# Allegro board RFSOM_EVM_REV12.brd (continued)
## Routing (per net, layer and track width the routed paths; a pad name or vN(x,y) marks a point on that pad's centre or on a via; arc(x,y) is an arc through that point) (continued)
TX_03_N: length 58.2
  TOP w0.114: J1.G26 223.02,60.02 ; 187.76,91.38 187.54,91.15 arc(187.42,91.08) 187.29,91.05 186.86,91.05 arc(186.73,91.08) 186.62,91.15 LAB18.2 186.07,91.15 arc(185.96,91.08) 185.83,91.05 185.7,91.05 arc(185.56,91.08) 185.45,91.15 LAB17.2
  ART03 w0.102: 223.02,60.02 223.02,59.75 arc(222.95,59.58) 222.77,59.51 218.88,59.51 arc(218.58,59.56) 218.32,59.73 202.06,76 arc(201.89,76.25) 201.83,76.55 201.83,85.13 arc(201.75,85.51) 201.53,85.84 196.64,90.74 arc(196.31,90.96) 195.92,91.04 188.33,91.04 arc(188.12,91.08) 187.94,91.2 187.76,91.38
TX_03_P: length 58.2
  TOP w0.114: J1.F26 223.02,58.75 ; LAB19.2 185.45,90.68 arc(185.56,90.76) 185.7,90.78 185.83,90.78 arc(185.96,90.76) 186.07,90.68 LAB18.1 186.62,90.68 arc(186.73,90.76) 186.86,90.78 187.29,90.78 arc(187.42,90.76) 187.54,90.68 187.76,90.46
  ART03 w0.102: 223.02,58.75 223.02,59.02 arc(222.95,59.2) 222.77,59.27 218.88,59.27 arc(218.49,59.35) 218.16,59.57 201.89,75.83 arc(201.67,76.16) 201.59,76.55 201.59,85.13 arc(201.53,85.42) 201.36,85.68 196.47,90.57 arc(196.22,90.74) 195.92,90.8 188.33,90.8 arc(188.12,90.76) 187.94,90.64 187.76,90.46
TX_04_N: length 71.1
  TOP w0.114: 187.76,101.38 187.59,101.21 arc(187.42,101.09) 187.22,101.05 186.95,101.05 arc(186.73,101.1) 186.55,101.22 LAB23.2 186.11,101.19 arc(185.95,101.09) 185.77,101.05 185.75,101.05 arc(185.57,101.09) 185.41,101.19 LAB22.2 ; J1.C22 228.1,65.1
  ART03 w0.102: 228.1,65.1 228.1,64.83 arc(228.03,64.66) 227.85,64.59 226.54,64.59 arc(226.15,64.51) 225.82,64.29 225.73,64.2 arc(225.51,63.87) 225.44,63.48 225.44,62.95 arc(225.38,62.65) 225.21,62.4 225.13,62.32 arc(224.87,62.15) 224.57,62.09 220.18,62.09 arc(219.88,62.15) 219.62,62.32 205.71,76.23 arc(205.55,76.48) 205.49,76.78 205.49,90.74 arc(205.41,91.13) 205.19,91.46 195.91,100.74 arc(195.58,100.96) 195.19,101.04 188.33,101.04 arc(188.12,101.08) 187.94,101.2 187.76,101.38
TX_04_P: length 71.1
  TOP w0.114: LAB24.2 185.41,100.65 arc(185.57,100.75) 185.75,100.78 185.77,100.78 arc(185.95,100.75) 186.11,100.65 LAB23.1 186.55,100.62 arc(186.73,100.74) 186.95,100.78 187.22,100.78 arc(187.42,100.74) 187.59,100.63 187.76,100.46 ; J1.B22 228.1,63.83
  ART03 w0.102: 187.76,100.46 187.94,100.64 arc(188.12,100.76) 188.33,100.8 195.19,100.8 arc(195.49,100.74) 195.75,100.57 205.02,91.3 arc(205.19,91.04) 205.25,90.74 205.25,76.78 arc(205.33,76.39) 205.55,76.06 219.46,62.15 arc(219.79,61.93) 220.18,61.85 224.57,61.85 arc(224.96,61.93) 225.29,62.15 225.38,62.23 arc(225.6,62.56) 225.67,62.95 225.67,63.48 arc(225.73,63.78) 225.9,64.03 225.99,64.12 arc(226.24,64.29) 226.54,64.35 227.85,64.35 arc(228.03,64.28) 228.1,64.1 228.1,63.83
TX_05_N: length 69.6
  TOP w0.114: J1.G22 223.02,65.1 ; 187.76,111.38 187.59,111.21 arc(187.42,111.09) 187.22,111.05 186.95,111.05 arc(186.73,111.1) 186.55,111.22 LAB28.2 186.11,111.19 arc(185.95,111.09) 185.77,111.05 185.75,111.05 arc(185.57,111.09) 185.41,111.19 LAB27.2
  ART03 w0.102: 187.76,111.38 187.94,111.2 arc(188.12,111.08) 188.33,111.04 192.63,111.04 arc(193.02,110.96) 193.35,110.74 208.85,95.24 arc(209.07,94.91) 209.14,94.52 209.14,76.98 arc(209.2,76.68) 209.37,76.43 220.99,64.81 arc(221.24,64.64) 221.54,64.59 222.77,64.59 arc(222.95,64.66) 223.02,64.83 223.02,65.1
TX_05_P: length 69.6
  TOP w0.114: LAB29.2 185.41,110.65 arc(185.57,110.75) 185.75,110.78 185.77,110.78 arc(185.95,110.75) 186.11,110.65 LAB28.1 186.55,110.62 arc(186.73,110.74) 186.95,110.78 187.22,110.78 arc(187.42,110.74) 187.59,110.63 187.76,110.46 ; J1.F22 223.02,63.83
  ART03 w0.102: 187.76,110.46 187.94,110.64 arc(188.12,110.76) 188.33,110.8 192.63,110.8 arc(192.93,110.74) 193.18,110.57 208.68,95.08 arc(208.85,94.82) 208.91,94.52 208.91,76.98 arc(208.98,76.59) 209.21,76.26 220.82,64.65 arc(221.15,64.43) 221.54,64.35 222.77,64.35 arc(222.95,64.28) 223.02,64.1 223.02,63.83
TX_06_N: length 82.2
  TOP w0.114: LAB32.2 185.41,121.19 arc(185.57,121.09) 185.75,121.05 185.77,121.05 arc(185.95,121.09) 186.11,121.19 LAB33.2 186.55,121.22 arc(186.73,121.1) 186.95,121.05 187.22,121.05 arc(187.42,121.09) 187.59,121.21 187.76,121.38 ; J1.C18 228.1,70.18
  ART03 w0.102: 228.1,70.18 228.1,69.91 arc(228.03,69.74) 227.85,69.67 226.35,69.67 arc(225.96,69.59) 225.63,69.37 225.45,69.18 arc(225.23,68.85) 225.15,68.46 225.15,67.94 arc(225.09,67.64) 224.92,67.39 224.88,67.35 arc(224.63,67.19) 224.33,67.13 222.94,67.13 arc(222.64,67.19) 222.39,67.35 213.82,75.92 arc(213.66,76.17) 213.6,76.47 213.6,98.86 arc(213.52,99.25) 213.3,99.58 192.14,120.74 arc(191.81,120.96) 191.42,121.04 188.33,121.04 arc(188.12,121.08) 187.94,121.2 187.76,121.38
TX_06_P: length 82.2
  TOP w0.114: 187.76,120.46 187.59,120.63 arc(187.42,120.74) 187.22,120.78 186.95,120.78 arc(186.73,120.74) 186.55,120.62 LAB33.1 186.11,120.65 arc(185.95,120.75) 185.77,120.78 185.75,120.78 arc(185.57,120.75) 185.41,120.65 LAB34.2 ; J1.B18 228.1,68.91
  ART03 w0.102: 228.1,68.91 228.1,69.18 arc(228.03,69.36) 227.85,69.43 226.35,69.43 arc(226.05,69.37) 225.8,69.2 225.61,69.02 arc(225.44,68.76) 225.38,68.46 225.38,67.94 arc(225.31,67.55) 225.09,67.22 225.05,67.19 arc(224.72,66.97) 224.33,66.89 222.94,66.89 arc(222.55,66.97) 222.22,67.19 213.66,75.75 arc(213.44,76.08) 213.36,76.47 213.36,98.86 arc(213.3,99.16) 213.13,99.41 191.97,120.57 arc(191.72,120.74) 191.42,120.8 188.33,120.8 arc(188.12,120.76) 187.94,120.64 187.76,120.46
TX_07_N: length 83.5
  TOP w0.114: J1.G18 223.02,70.18 ; 187.76,131.38 187.59,131.21 arc(187.42,131.09) 187.22,131.05 186.95,131.05 arc(186.73,131.1) 186.55,131.22 LAB38.2 186.11,131.19 arc(185.95,131.09) 185.77,131.05 185.75,131.05 arc(185.57,131.09) 185.41,131.19 LAB37.2
  ART03 w0.102: 187.76,131.38 187.94,131.2 arc(188.12,131.08) 188.33,131.04 192.37,131.04 arc(192.76,130.96) 193.09,130.74 196.03,127.8 arc(196.25,127.47) 196.32,127.08 196.32,122.19 arc(196.38,121.89) 196.55,121.64 217.06,101.13 arc(217.28,100.8) 217.36,100.41 217.36,76.85 arc(217.41,76.55) 217.58,76.29 222.1,71.77 arc(222.33,71.44) 222.4,71.05 222.4,69.86 arc(222.46,69.72) 222.59,69.67 222.77,69.67 arc(222.95,69.74) 223.02,69.91 223.02,70.18
TX_07_P: length 83.5
  TOP w0.114: J1.F18 223.02,68.91 ; LAB39.2 185.41,130.65 arc(185.57,130.75) 185.75,130.78 185.77,130.78 arc(185.95,130.75) 186.11,130.65 LAB38.1 186.55,130.62 arc(186.73,130.74) 186.95,130.78 187.22,130.78 arc(187.42,130.74) 187.59,130.63 187.76,130.46
  ART03 w0.102: 223.02,68.91 223.02,69.18 arc(222.95,69.36) 222.77,69.43 222.59,69.43 arc(222.29,69.55) 222.17,69.86 222.17,71.05 arc(222.11,71.35) 221.94,71.61 217.42,76.13 arc(217.2,76.46) 217.12,76.85 217.12,100.41 arc(217.06,100.71) 216.89,100.96 196.39,121.47 arc(196.17,121.8) 196.09,122.19 196.09,127.08 arc(196.03,127.38) 195.86,127.64 192.92,130.57 arc(192.67,130.74) 192.37,130.8 188.33,130.8 arc(188.12,130.76) 187.94,130.64 187.76,130.46
TXD_GPS: length 313.8
  TOP w0.173: J1.B13 v1(229.37,76.53) ; J2.B9 v1(328.33,81.61) ; RG2.1 232.54,-23.98 v1(232.59,-24.03)
  ART03 w0.135: v1(229.37,76.53) 230.31,75.59 230.31,5.13 228.36,3.18 228.36,-8.66 232.59,-12.9 v1(232.59,-24.03)
  ART10 w0.135: v1(328.33,81.61) 328.97,81.61 330.03,80.55 330.03,68.52 329.65,68.13 318.64,68.13 316.17,65.66 316.17,-21.65 313.79,-24.04 282.45,-24.04 278.65,-20.23 270.47,-20.23 266.1,-24.6 244.69,-24.6 241.21,-21.13 235.5,-21.13 v1(232.59,-24.03)
UART0_RX: length 137.6
  TOP w0.173: J2.B13 v1(328.33,76.53) ; U7.4 381,16.86 v1(381.25,17.12)
  ART05 w0.14: v1(381.25,17.12) 381.96,17.82 388.74,17.82 389.26,17.3 390.74,17.3 391.34,17.89 391.34,19.21 385.97,24.59 385.97,40.07 385.29,40.74 381.66,40.74 380.85,41.55 380.85,42.75 381.18,43.08 381.18,43.77 379.6,45.34 372.07,45.34 369.94,47.47 369.94,52.79 368.65,54.08 368.65,56.8 366.68,58.77 366.68,67.81 368.53,69.66 368.53,78.54 362.65,84.42 339.17,84.42 330.62,75.87 329,75.87 v1(328.33,76.53)
UART0_TX: length 121.3
  TOP w0.173: v1(378.46,17.12) 378.2,16.86 U8.4 ; J2.F11 v1(323.25,79.07)
  BOTTOM w0.173: v1(323.25,79.07) 322.73,79.6 317.03,79.6 315.31,77.88 315.31,62.03 319.1,58.24 329.79,58.24 332.24,55.79 344.76,55.79 350.38,50.18 350.38,45.12 353.42,42.09 370.59,42.09 378.46,34.21 v1(378.46,17.12)
USB_5V: length 3.8
  TOP w0.381: D10.2 v1(389.59,33.18) ; U17.6 v1(392.89,29.51) ; U17.8 v1(392.89,32.05)
  vias: v1(386.82,42.14) v1(386.82,41.48) v1(387.38,43.05) v1(388.04,43.05)
USB_CLK: length 1.7
  TOP w0.173: U15.26 383.55,42.8 R70.1
USB_CLKOUT: length 138.9
  TOP w0.173: J2.C19 v1(325.79,68.91) ; U15.1 378.52,40.56 v1(378.03,41.06)
  BOTTOM w0.173: v1(378.03,41.06) 378.03,43.17 380.43,45.58 380.43,52.77 381.5,53.84 385.17,53.84 388.29,56.96 388.29,64.59 386,66.88 380.8,66.88 380.45,67.23 380.45,67.7 380.11,68.04 379.33,68.04 378.93,68.44 378.93,69.38 378.7,69.61 378.7,71.75 376.41,74.04 372.46,74.04 367.62,78.88 361.67,78.88 359.73,76.94 354.24,76.94 351.03,80.15 344.56,80.15 342.9,81.82 330.45,81.82 329.57,80.94 326.78,80.94 326.3,80.46 326.3,77.53 325.93,77.17 325.65,77.17 325.22,76.73 325.22,76.45 324.61,75.84 324.26,75.84 323.88,75.46 323.88,75.11 323.59,74.82 318.81,74.82 317.78,73.79 317.78,65.93 319.06,64.66 323.45,64.66 324.33,65.54 324.35,65.54 325.13,66.33 325.13,68.25 v1(325.79,68.91)
USB_CPEN: length 6.3
  TOP w0.173: U15.17 384.75,32.65 385.34,32.05 U17.1
USB_DATA0: length 87.6
  TOP w0.173: U15.3 378.53,39.56 v1(378.03,40.06) ; J2.D16 v1(325.79,71.45)
  ART05 w0.14: v1(325.79,71.45) 326.22,71.02 330.15,71.02 335.69,76.56 358.27,76.56 363.28,71.55 363.28,59.64 366.5,56.42 366.5,42.98 369.42,40.06 v1(378.03,40.06)
USB_DATA1: length 69.9
  TOP w0.173: J2.B19 v1(328.33,68.91) ; U15.4 378.53,39.06 v1(378.03,38.56)
  BOTTOM w0.173: v1(378.03,38.56) 370.19,46.39 370.19,54.44 367.15,57.47 344.82,57.47 336.98,65.32 332.91,65.32 329.98,68.25 329,68.25 v1(328.33,68.91)
USB_DATA2: length 109.7
  TOP w0.173: J2.D18 v1(324.52,68.91) ; v1(379.03,38.56) U15.5
  ART05 w0.14: v1(324.52,68.91) 324.52,68.57 324.98,68.11 331.68,68.11 337.99,74.42 354.99,74.42 359.38,70.03 359.38,54 364.25,49.12 364.25,35.73 369.72,30.26 380.96,30.26 383.68,32.99 383.68,35.8 383.07,36.42 380.49,36.42 379.77,37.14 379.77,37.82 v1(379.03,38.56)
USB_DATA3: length 90
  TOP w0.173: J2.E16 v1(324.52,71.45) ; U15.6 378.53,38.06 v1(378.03,37.56)
  ART05 w0.14: v1(378.03,37.56) 370.35,37.56 365.94,41.97 365.94,56.25 362.31,59.88 362.31,71.31 357.59,76.03 336.05,76.03 330.63,70.61 325.36,70.61 v1(324.52,71.45)
USB_DATA4: length 94.4
  TOP w0.173: v1(379.03,37.56) U15.7 ; J2.G15 v1(321.98,73.99)
  ART05 w0.14: v1(379.03,37.56) 379.03,37.83 378.58,38.27 378.58,38.91 379.52,39.86 379.52,40.75 378.47,41.8 369.77,41.8 367.06,44.51 367.06,56.76 364.03,59.8 364.03,72.02 361.75,74.3 361.75,74.3 358.95,77.1 334.5,77.1 330.56,73.15 322.82,73.15 v1(321.98,73.99)
USB_DATA5: length 74.9
  TOP w0.173: J2.B21 v1(328.33,66.37) ; U15.9 v1(380.55,35.54)
  BOTTOM w0.173: v1(380.55,35.54) 380.55,37 379.53,38.02 377.01,38.02 369.06,45.98 369.06,54.01 366.07,57 334.44,57 330.68,60.76 330.68,65.29 330.26,65.71 329,65.71 v1(328.33,66.37)
USB_DATA6: length 100
  TOP w0.173: U15.10 381.05,35.04 v1(380.54,34.54) ; J2.G17 v1(320.71,71.45)
  ART05 w0.14: v1(380.54,34.54) 369.23,34.54 364.81,38.95 364.81,49.72 360.65,53.88 360.65,70.53 356.23,74.96 337.65,74.96 331.16,68.47 325.57,68.47 324.7,69.34 324.7,69.34 324.45,69.6 321.62,69.6 321.28,69.94 321.28,70.88 v1(320.71,71.45)
USB_DATA7: length 98.8
  TOP w0.173: v1(382.04,34.54) 382.55,35.04 U15.13 ; J2.F17 v1(321.98,71.45)
  ART05 w0.14: v1(382.04,34.54) 381.93,34.65 381.93,34.66 381.56,35.02 370.75,35.02 365.38,40.39 365.38,50.42 361.67,54.13 361.67,70.73 356.91,75.49 337.3,75.49 331.34,69.53 325.84,69.53 325.62,69.75 324.71,70.66 322.78,70.66 v1(321.98,71.45)
USB_DIR: length 122.9
  TOP w0.173: J2.D20 v1(324.52,67.64) ; U15.31 381.05,42.49 v1(379.98,43.56)
  ART05 w0.14: v1(379.98,43.56) 379.58,43.15 379.58,41.32 380.5,40.4 380.5,37.08 380.71,36.88 383.46,36.88 384.58,35.75 384.58,31.53 381.41,28.35 365.77,28.35 363.69,30.43 363.69,48.74 358.66,53.78 358.66,64.53 357.04,66.15 357.04,71.36 354.51,73.89 338.48,73.89 331.68,67.09 325.08,67.09 v1(324.52,67.64)
USB_DM: length 22.4
  TOP w0.142: U15.19 385.4,38.06 385.51,37.96 387.82,37.96 D9.3
  TOP w0.152: v1(391.11,38.63) 391.41,38.33 391.41,38.13 391.26,37.97 389.45,37.97 D9.3
  ART03 w0.127: v1(391.11,38.63) 391.44,38.96 391.44,39.6 391.84,40 395.56,40 397.05,41.49 397.05,42.36 396.9,42.51 396.81,42.51 396.67,42.66 396.67,42.87 396.81,43.02 396.9,43.02 397.05,43.16 397.05,43.38 396.9,43.52 396.81,43.52 396.67,43.67 396.67,43.88 396.81,44.03 396.9,44.03 397.05,44.18 397.05,44.51 396.87,44.69 395.12,44.69 394.99,44.56 J18.2
USB_DP: length 22.5
  TOP w0.142: U15.18 385.4,37.56 385.51,37.66 387.82,37.66 D10.3
  TOP w0.152: v1(392.02,38.63) 391.72,38.33 391.72,38 391.39,37.67 389.47,37.67 D10.3
  ART03 w0.127: v1(392.02,38.63) 391.69,38.96 391.69,39.5 391.95,39.75 395.67,39.75 397.31,41.39 397.31,44.62 396.98,44.95 395.12,44.95 394.99,45.07 J18.3
USB_ID: length 3.4
  TOP w0.173: U15.23 385.2,40.06 385.6,40.46 R69.2
USB_NXT: length 89.3
  TOP w0.173: J2.E18 v1(323.25,70.18) ; v1(379.03,40.06) 379.03,40.06 U15.2
  BOTTOM w0.173: v1(379.03,40.06) 378.55,40.54 377.22,40.54 371.13,46.63 371.13,58.24 374.04,61.16 374.04,61.56 373.79,61.81 373.79,62.45 374.14,62.8 374.46,62.8 375.35,63.69 375.35,64.2 375.02,64.53 367.59,64.53 365.61,62.55 343.72,62.55 338.53,67.75 333.85,67.75 330.59,71.01 327.34,71.01 326.06,69.72 323.71,69.72 v1(323.25,70.18)
USB_RESET#: length 119.8
  TOP w0.173: J2.E8 v1(323.25,82.88) ; v1(382.55,43.56) 383.05,43.06 U15.27
  ART05 w0.14: v1(382.55,43.56) 382.55,47.65 384.8,49.91 384.8,81.76 370.37,96.19 335.25,96.19 330.31,91.25 330.3,91.24 325.73,91.24 325.22,90.73 325.22,84.85 v1(323.25,82.88)
  BOTTOM w0.173: R66.2 382.41,43.43 v1(382.55,43.56)
USB_RX_N: length 13.4
  TOP w0.152: C92.1 384.68,52.53 385.13,52.08 385.64,52.08 385.72,52.17 U18.1 U18.8 387.75,52.17 387.86,52.07 389.89,52.07 390.86,51.1 390.86,48.41 391.3,47.97 393.34,47.97 393.49,48.12 J18.5
USB_RX_P: length 13.3
  TOP w0.152: J18.6 393.49,47.51 393.34,47.67 391.17,47.67 390.55,48.29 390.55,50.98 389.76,51.77 387.86,51.77 387.75,51.66 U18.7 U18.2 385.72,51.66 385.61,51.78 384.85,51.78 384.66,51.59 C95.1
USB_STP: length 101.2
  TOP w0.173: v1(380.75,43.56) 382.05,42.26 U15.29 ; J2.F15 v1(323.25,73.99)
  ART05 w0.14: v1(323.25,73.99) 325.1,73.99 325.78,74.68 330.43,74.68 339.75,84 361.92,84 367.64,78.28 367.64,70 365.63,68 365.63,59.05 368.02,56.67 368.02,54.07 369.32,52.77 369.32,46.79 371.28,44.83 379.48,44.83 v1(380.75,43.56)
USB_TX_N: length 8.3
  TOP w0.142: U18.3 U18.6
  TOP w0.152: U18.3 385.72,50.44 385.62,50.34 384.84,50.34 384.66,50.52 C97.1 ; C88.1 389.78,46.95 389.44,47.29 389.44,49.27 388.37,50.34 387.86,50.34 387.75,50.44 U18.6
USB_TX_P: length 8.2
  TOP w0.142: U18.4 U18.5
  TOP w0.152: C96.1 384.45,49.58 384.9,50.03 385.63,50.03 385.72,49.94 U18.4 ; U18.5 387.75,49.94 387.86,50.04 388.24,50.04 389.14,49.14 389.14,48.64 388.81,48.32 388.81,48.03 389.14,47.71 389.14,47.35 388.8,47.01 C89.1
USER_IO0: length 155.3
  TOP w0.173: J1.C11 v1(228.1,79.07)
  ART10 w0.135: J11.2 182.67,-25.15 205.17,-25.15 219.65,-10.67 219.65,7.62 237.59,25.56 237.59,74.73 233.96,78.36 228.81,78.36 v1(228.1,79.07)
USER_IO1: length 185.1
  TOP w0.173: J1.F9 v1(223.02,81.61)
  ART05 w0.14: J11.3 179.51,-31.5 181.03,-33.02 221.07,-33.02 223.91,-30.18 223.91,-26.36 244.65,-5.62 244.65,72.69 237.6,79.74 225.19,79.74 223.32,81.61 v1(223.02,81.61)
USER_IO2: length 180.4
  TOP w0.173: J1.G9 v1(221.75,81.61)
  ART05 w0.14: J11.4 181.51,-30.61 183.49,-32.6 220.01,-32.6 222.9,-29.72 222.9,-25.77 242.54,-6.13 242.54,72.74 236.92,78.35 225.42,78.35 224.94,78.84 224.94,79.14 224.44,79.64 222.84,79.64 222.34,80.13 222.34,81.02 v1(221.75,81.61)
USER_IO3: length 141.2
  TOP w0.173: J1.D14 v1(225.56,73.99)
  ART05 w0.14: v1(225.56,73.99) 226.12,73.43 230.5,73.43 235.45,68.47 235.45,15.16 194.19,-26.11 188.38,-26.11 186.51,-27.98 186.51,-31.6 186.1,-32.01 184.29,-32.01 183.51,-31.22 J11.5
USER_IO4: length 136.2
  TOP w0.173: J1.E14 v1(224.29,73.99)
  ART05 w0.14: v1(224.29,73.99) 224.92,73.36 224.92,72.44 225.22,72.13 230.27,72.13 234.37,68.03 234.37,15.59 193.68,-25.1 187.57,-25.1 185.51,-27.16 J11.6
USER_IO5: length 143.5
  TOP w0.173: J1.F11 v1(223.02,77.8)
  ART05 w0.14: v1(223.02,77.8) 222.57,77.35 222.57,76.06 224.21,74.42 231.57,74.42 236.94,69.06 236.94,14.62 195.36,-26.96 189.31,-26.96 187.51,-28.76 J11.7
USER_IO6: length 144.5
  TOP w0.173: J1.G11 v1(223.02,79.07)
  ART05 w0.14: J11.8 189.51,-29.29 191.18,-27.61 196.93,-27.61 238.06,13.52 238.06,69.22 232.31,74.97 224.68,74.97 223.47,76.18 223.47,78.62 v1(223.02,79.07)
USER_IO7: length 142.4
  TOP w0.173: J1.F13 v1(224.29,76.53)
  ART05 w0.14: v1(224.29,76.53) 225.37,75.45 233.98,75.45 239.37,70.05 239.37,12.98 198.13,-28.26 192.07,-28.26 191.51,-28.82 J11.9
USER_IOB0: length 78.7
  TOP w0.173: J1.C9 v1(226.83,81.61)
  ART05 w0.14: v1(226.83,81.61) 226.17,81.61 224.98,82.8 224.98,84.11 225.66,84.8 227.01,84.8 227.45,85.23 227.45,108.27 221.49,114.22 211.94,114.22 204.38,121.78 J9.1
USER_IOB1: length 77.3
  TOP w0.173: J1.D8 v1(225.56,82.88)
  ART05 w0.14: J9.2 206.38,120.67 212.06,114.99 222.33,114.99 228.67,108.65 228.67,83.59 228.52,83.45 226.12,83.45 v1(225.56,82.88)
USER_IOB2: length 82.5
  TOP w0.173: J1.E8 v1(224.29,82.88)
  ART05 w0.14: J9.3 208.38,119.94 212.45,115.87 223.16,115.87 229.99,109.04 229.99,82.61 229.61,82.22 228.19,82.22 227.06,81.09 225.03,81.09 224.29,81.83 v1(224.29,82.88)
USER_IOB3: length 81.1
  TOP w0.173: J1.D10 v1(226.83,80.34)
  ART05 w0.14: J9.4 210.38,118.7 212.57,116.51 224.21,116.51 231.14,109.58 231.14,81.25 230.73,80.84 227.73,80.84 227.23,80.34 v1(226.83,80.34)
USER_IOB4: length 71.9
  TOP w0.173: J1.E10 v1(224.29,79.07)
  ART10 w0.135: J9.5 212.38,140.6 213.74,139.25 213.74,83.85 219.09,78.5 223.71,78.5 v1(224.29,79.07)
USER_IOB5: length 74.5
  TOP w0.173: J1.D12 v1(226.83,77.8)
  ART10 w0.135: v1(226.83,77.8) 226.2,77.18 225.21,77.18 224.92,77.47 224.92,79.15 224.4,79.67 219.05,79.67 217.12,81.59 217.12,97.49 214.84,99.76 214.84,140.86 J9.6
USER_IOB6: length 73
  TOP w0.173: J1.E12 v1(225.56,77.8)
  ART10 w0.135: v1(225.56,77.8) 226.19,78.43 226.19,80.37 225.5,81.05 218.65,81.05 217.93,81.77 217.93,97.84 216.03,99.75 216.03,140.96 J9.7
USER_IOB7: length 73.1
  TOP w0.114: J1.B11 v1(229.37,79.07)
  ART10 w0.135: v1(229.37,79.07) 228.73,79.71 228.73,81.28 227.75,82.26 219.91,82.26 218.8,83.37 218.8,98.27 217.35,99.72 217.35,140.28 J9.8
ZQSFP_VCC: length 9.8
  TOP w0.381: J12.30 352.1,83.93 351.46,83.29 C34.1 C33.1 FB3.2
ZQSFP_VCCRX: length 8.2
  TOP w0.381: J12.10 v1(360.34,85.13)
  BOTTOM w0.508: FB4.2 C35.1 363.44,83.29 362.86,83.87 C36.1 361.59,83.87 v1(360.34,85.13)
ZQSFP_VCCTX: length 9.8
  TOP w0.381: FB5.2 C37.1 C38.1 351.46,85.37 352.1,84.73 J12.29
N21034969: length 21.5
  TOP w0.173: UG1.9 v1(226.74,-4.73)
  BOTTOM w0.173: RG1.1 234.14,-17.02 226.74,-9.62 v1(226.74,-4.73)
N21034983: length 28
  TOP w0.173: UG1.11 v1(224.54,-4.73)
  BOTTOM w0.173: v1(224.54,-4.73) 224.54,-11.28 230.25,-16.99 LG1.2 JA17.1
N21034987: length 2.4
  BOTTOM w0.173: RG1.2 CG1.1 LG1.1
N22362940: length 2.1
  TOP w0.173: R70.2 383.63,44.14 384.37,44.87 X1.3
N22363153: length 2.5
  TOP w0.173: D11.2 U17.2
N22481513:
  vias: v1(361.47,-3.68) v1(361.47,-4.68) v1(361.47,-5.68) v1(361.47,-6.68) v1(362.47,-3.68) v1(362.47,-4.68) v1(362.47,-5.68) v1(362.47,-6.68) v1(363.47,-3.68) v1(363.47,-4.68) v1(363.47,-5.68) v1(363.47,-6.68) v1(364.47,-3.68) v1(364.47,-4.68) v1(364.47,-5.68) v1(364.47,-6.68)
N22481515:
  vias: v1(363.67,-13.74) v1(363.67,-14.74) v1(363.67,-15.74) v1(363.67,-16.74) v1(363.67,-17.74) v1(364.67,-13.74) v1(364.67,-14.74) v1(364.67,-15.74) v1(364.67,-16.74) v1(364.67,-17.74) v1(365.67,-13.74) v1(365.67,-14.74) v1(365.67,-15.74) v1(365.67,-16.74) v1(365.67,-17.74) v1(366.67,-13.74) v1(366.67,-14.74) v1(366.67,-15.74) v1(366.67,-16.74) v1(366.67,-17.74)
N22531080: length 2.1
  TOP w0.173: U9.4 v1(395.77,3.24)
  BOTTOM w0.173: v1(395.77,3.24) 395.33,2.8 C29.1
N22531228: length 1.6
  TOP w0.173: R18.1 385.91,-3.04 385.55,-3.4 U10.4
N22531283: length 1.7
  TOP w0.173: R21.2 D3.1
N22533284: length 1.4
  TOP w0.381: U19.F6 v1(236.66,127.43)
  BOTTOM w0.381: RP4.2 236.32,127.09 v1(236.66,127.43)
N22533286: length 1.4
  TOP w0.381: U19.J6 v1(241.74,127.43)
  BOTTOM w0.508: RP5.2 241.41,127.1 v1(241.74,127.43)
N22533326: length 2.3
  TOP w0.381: U19.F2 v1(236.66,121.08)
  BOTTOM w0.381: RP9.2 238.05,121.08 v1(236.66,121.08)
N22533328: length 12.4
  BOTTOM w0.508: RP11.1 RP10.2 TP1.1 ; RP9.1 TP1.1 ; TP1.1 RP8.1 RP7.1
N22533342: length 5
  TOP w0.381: U19.A6 v1(230.31,127.43) ; U19.K6 v1(243.01,127.43) ; U19.G6 v1(239.2,127.43) ; U19.D6 v1(234.12,127.43)
  BOTTOM w0.508: COUT5.1 234.12,127.47 v1(234.12,127.43)
N22533629: length 7.9
  TOP w0.381: U19.E7 236.03,129.86 235.43,130.45 C105.1 232.74,130.45 232.22,129.93 U19.B7
N22533693: length 4.3
  TOP w0.381: U19.A7 v1(230.31,128.7) ; U19.D7 v1(234.12,128.7) ; U19.G7 v1(239.2,128.7) ; U19.J7 v1(241.74,128.7)
  BOTTOM w0.508: RP1.1 v1(239.2,128.7)
N22533770: length 1.4
  TOP w0.381: U19.C6 v1(232.85,127.43)
  BOTTOM w0.381: RP3.2 232.51,127.09 v1(232.85,127.43)
N22533812: length 2.6
  TOP w0.381: U19.K7 v1(243.01,128.7)
  BOTTOM w0.381: RP6.2 242.13,129.58 v1(243.01,128.7)
N22533845: length 1.7
  TOP w0.381: U19.C3 v1(232.85,122.35)
  BOTTOM w0.381: RP7.2 232.87,122.37 v1(232.85,122.35)
N22533851: length 3.5
  TOP w0.381: U19.C2 v1(232.85,121.08)
  BOTTOM w0.381: RP8.2 233.48,122.67 233.48,121.71 v1(232.85,121.08)
N22533867: length 1.5
  TOP w0.381: U19.J2 v1(241.74,121.08)
  BOTTOM w0.508: RP11.2 241.66,121.16 v1(241.74,121.08)
N22533883: length 2.7
  TOP w0.381: C106.1 240.47,130.47 240.47,128.7 U19.H7
N22533912: length 1.6
  TOP w0.381: U19.F3 v1(236.66,122.35)
  BOTTOM w0.508: v1(236.66,122.35) 236.61,122.4 RP12.2
N22533999: length 2.7
  TOP w0.381: U19.L7 244.33,128.75 C107.1
N22534068: length 1
  BOTTOM w0.508: RP2.1 RP1.2
N22535757: length 0.7
  BOTTOM w0.381: R97.2 v1(362.7,47.66)
N22535954: length 1
  TOP w0.508: R102.2 312.75,112.72
N22536146: length 1.4
  BOTTOM w0.508: R95.2 R96.1
N22536167: length 1.9
  TOP w0.381: U20.4 v1(362.7,44.16)
  BOTTOM w0.508: R95.1 363.72,44.16 v1(362.7,44.16)
N22536169: length 1.7
  TOP w0.381: U20.5 v1(362.7,45.36)
  BOTTOM w0.508: R97.1 v1(362.7,45.36)
N22536187: length 2.3
  TOP w0.381: U20.11 354.09,44.16 R99.1
N22536481: length 1.6
  TOP w0.508: R100.2 R101.1
N22536506: length 2.5
  TOP w0.508: U21.4 R100.1
N22536508: length 2.5
  TOP w0.508: R102.1 U21.5
N22536526: length 2.7
  TOP w0.508: R104.1 310.11,122.3 309.74,121.94 U21.11
N22545864: length 4
  TOP w0.114: LAB32.1 183.89,121.15 arc(183.78,121.08) 183.65,121.05 182.44,121.05 arc(182.34,121.07) 182.25,121.1 arc(182.22,121.13) 182.2,121.15
  TOP w0.173: 182.2,121.15 181.55,121.8 arc(181.16,122.05) TAB7.4
N22545929: length 3.1
  TOP w0.483: TAB7.3 CAB40.1
N22545941: length 2
  TOP w0.483: CAB40.2 RAB27.1 RAB26.1
N22545947: length 2.1
  TOP w0.483: RAB26.2 RAB28.1 CAB42.1
N22545953: length 9.6
  TOP w0.483: JA7.1 CAB42.2
N22545955: length 4
  TOP w0.114: LAB34.1 183.89,120.68 arc(183.78,120.76) 183.65,120.78 182.44,120.78 arc(182.34,120.77) 182.26,120.73 arc(182.23,120.71) 182.2,120.68
  TOP w0.173: 182.2,120.68 181.4,119.89 arc(181.09,119.68) TAB7.6
N22546147: length 4
  TOP w0.114: LAB37.1 183.89,131.15 arc(183.78,131.08) 183.65,131.05 182.44,131.05 arc(182.36,131.06) 182.29,131.09 arc(182.27,131.09) 182.25,131.1 arc(182.22,131.13) 182.2,131.15
  TOP w0.173: 182.2,131.15 181.55,131.8 arc(181.16,132.05) TAB8.4
N22546214: length 3.1
  TOP w0.483: TAB8.3 CAB46.1
N22546226: length 2
  TOP w0.483: CAB46.2 RAB31.1 RAB30.1
N22546232: length 2.1
  TOP w0.483: RAB30.2 RAB32.1 CAB48.1
N22546238: length 9.6
  TOP w0.483: CAB48.2 JA8.1
N22546240: length 4
  TOP w0.114: LAB39.1 183.89,130.68 arc(183.78,130.76) 183.65,130.78 182.44,130.78 arc(182.34,130.77) 182.26,130.73 arc(182.23,130.71) 182.2,130.68
  TOP w0.173: 182.2,130.68 181.4,129.89 arc(181.09,129.68) TAB8.6
N22613335: length 8.2
  TOP w0.381: J5.2 284.63,-26.3 283.03,-24.69 Q1.3 D4.2
N22613341: length 8.2
  TOP w0.381: D5.2 Q2.3 291.9,-24.79 293.5,-26.39 J6.2
N22613343: length 8.2
  TOP w0.381: D6.2 Q3.3 300.76,-24.76 302.36,-26.37 J7.2
N22613345: length 8.2
  TOP w0.381: J8.2 311.23,-26.3 309.63,-24.69 Q4.3 D7.2
N22692224: length 4
  TOP w0.114: LAB2.1 183.89,61.15 arc(183.78,61.08) 183.65,61.05 182.44,61.05 arc(182.34,61.07) 182.25,61.1 arc(182.22,61.13) 182.2,61.15
  TOP w0.173: 182.2,61.15 181.55,61.8 arc(181.16,62.06) TAB1.4
N22692289: length 3.1
  TOP w0.483: TAB1.3 CAB4.1
N22692291: length 2
  TOP w0.483: RAB2.1 RAB3.1 CAB4.2
N22692307: length 2.1
  TOP w0.483: RAB2.2 RAB4.1 CAB6.1
N22692313: length 9.6
  TOP w0.483: CAB6.2 JA1.1
N22692315: length 4
  TOP w0.114: LAB4.1 183.89,60.68 arc(183.78,60.76) 183.65,60.78 182.44,60.78 arc(182.34,60.77) 182.26,60.73 arc(182.23,60.71) 182.2,60.68
  TOP w0.173: 182.2,60.68 181.4,59.89 arc(181.09,59.68) TAB1.6
N22692505: length 4
  TOP w0.114: LAB7.1 183.89,71.15 arc(183.78,71.08) 183.65,71.05 182.44,71.05 arc(182.34,71.07) 182.25,71.1 arc(182.22,71.13) 182.2,71.15
  TOP w0.173: 182.2,71.15 181.55,71.8 arc(181.16,72.06) TAB2.4
N22692570: length 3.1
  TOP w0.483: TAB2.3 CAB10.1
N22692582: length 2
  TOP w0.483: CAB10.2 RAB7.1 RAB6.1
N22692588: length 2.1
  TOP w0.483: RAB6.2 RAB8.1 CAB12.1
N22692594: length 9.6
  TOP w0.483: CAB12.2 JA2.1
N22692596: length 4
  TOP w0.114: LAB9.1 183.89,70.68 arc(183.78,70.76) 183.65,70.78 182.44,70.78 arc(182.34,70.77) 182.26,70.73 arc(182.23,70.71) 182.2,70.68
  TOP w0.173: 182.2,70.68 181.4,69.89 arc(181.09,69.68) TAB2.6
N22693543: length 4
  TOP w0.114: LAB12.1 183.89,81.15 arc(183.78,81.08) 183.65,81.05 182.44,81.05 arc(182.34,81.07) 182.25,81.1 arc(182.22,81.13) 182.2,81.15
  TOP w0.173: 182.2,81.15 181.55,81.8 arc(181.16,82.06) TAB3.4
N22693600: length 3.1
  TOP w0.483: TAB3.3 CAB16.1
N22693620: length 2
  TOP w0.483: CAB16.2 RAB11.1 RAB10.1
N22693626: length 2.1
  TOP w0.483: RAB10.2 RAB12.1 CAB18.1
N22693632: length 9.6
  TOP w0.483: CAB18.2 JA3.1
N22693634: length 4
  TOP w0.114: LAB14.1 183.89,80.68 arc(183.78,80.76) 183.65,80.78 182.44,80.78 arc(182.34,80.77) 182.26,80.73 arc(182.23,80.71) 182.2,80.68
  TOP w0.173: 182.2,80.68 181.4,79.89 arc(181.09,79.68) TAB3.6
N22693824: length 4
  TOP w0.114: LAB17.1 183.89,91.15 arc(183.78,91.08) 183.65,91.05 182.44,91.05 arc(182.34,91.07) 182.25,91.1 arc(182.22,91.13) 182.2,91.15
  TOP w0.173: 182.2,91.15 181.55,91.8 arc(181.16,92.06) TAB4.4
N22693889: length 3.1
  TOP w0.483: TAB4.3 CAB22.1
N22693901: length 2
  TOP w0.483: RAB14.1 RAB15.1 CAB22.2
N22693907: length 2.1
  TOP w0.483: RAB14.2 RAB16.1 CAB24.1
N22693913: length 9.6
  TOP w0.483: CAB24.2 JA4.1
N22693915: length 4
  TOP w0.114: LAB19.1 183.89,90.68 arc(183.78,90.76) 183.65,90.78 182.44,90.78 arc(182.34,90.77) 182.26,90.73 arc(182.23,90.71) 182.2,90.68
  TOP w0.173: 182.2,90.68 181.4,89.89 arc(181.09,89.68) TAB4.6
N22694836: length 4
  TOP w0.114: LAB22.1 183.89,101.15 arc(183.78,101.08) 183.65,101.05 182.44,101.05 arc(182.34,101.07) 182.25,101.1 arc(182.22,101.13) 182.2,101.15
  TOP w0.173: 182.2,101.15 181.55,101.8 arc(181.16,102.06) TAB5.4
N22694901: length 3.1
  TOP w0.483: TAB5.3 CAB28.1
N22694903: length 2
  TOP w0.483: CAB28.2 RAB19.1 RAB18.1
N22694919: length 2.1
  TOP w0.483: RAB18.2 RAB20.1 CAB30.1
N22694925: length 9.6
  TOP w0.483: CAB30.2 JA5.1
N22694927: length 4
  TOP w0.114: LAB24.1 183.89,100.68 arc(183.78,100.76) 183.65,100.78 182.44,100.78 arc(182.34,100.77) 182.26,100.73 arc(182.23,100.71) 182.2,100.68
  TOP w0.173: 182.2,100.68 181.4,99.89 arc(181.09,99.68) TAB5.6
N22695117: length 4
  TOP w0.114: LAB27.1 183.89,111.15 arc(183.78,111.08) 183.65,111.05 182.44,111.05 arc(182.34,111.07) 182.25,111.1 arc(182.22,111.13) 182.2,111.15
  TOP w0.173: 182.2,111.15 181.55,111.8 arc(181.16,112.06) TAB6.4
N22695182: length 3.1
  TOP w0.483: TAB6.3 CAB34.1
N22695184: length 2
  TOP w0.483: CAB34.2 RAB23.1 RAB22.1
N22695200: length 2.1
  TOP w0.483: CAB36.1 RAB24.1 RAB22.2
N22695206: length 9.6
  TOP w0.483: CAB36.2 JA6.1
N22695208: length 4
  TOP w0.114: LAB29.1 183.89,110.68 arc(183.78,110.76) 183.65,110.78 182.44,110.78 arc(182.34,110.77) 182.26,110.73 arc(182.23,110.71) 182.2,110.68
  TOP w0.173: 182.2,110.68 181.4,109.89 arc(181.09,109.68) TAB6.6
N22696156: length 5.4
  TOP w0.114: CAB49.2 185.05,-18.85 arc(184.94,-18.92) 184.81,-18.95 184.68,-18.95 arc(184.55,-18.92) 184.44,-18.85 LAB41.2 183.89,-18.85 arc(183.78,-18.92) 183.65,-18.95 182.44,-18.95 arc(182.34,-18.93) 182.25,-18.9 arc(182.22,-18.87) 182.2,-18.85
  TOP w0.173: 182.2,-18.85 181.55,-18.2 arc(181.16,-17.94) TAB9.4
N22696251: length 9.6
  TOP w0.483: CAA4.1 JA9.1
N22696263: length 2.1
  TOP w0.483: CAA4.2 RAA3.1 RAA2.1
N22696269: length 2
  TOP w0.483: RAA2.2 RAA4.1 CAB50.2
N22696275: length 3.1
  TOP w0.483: TAB9.3 CAB50.1
N22696283: length 5.5
  TOP w0.114: CAB51.2 185.05,-19.32 arc(184.94,-19.24) 184.81,-19.22 184.68,-19.22 arc(184.55,-19.24) 184.44,-19.32 LAB41.1 183.89,-19.32 arc(183.78,-19.24) 183.65,-19.22 182.44,-19.22 arc(182.34,-19.23) 182.26,-19.27 arc(182.23,-19.29) 182.2,-19.32
  TOP w0.173: 182.2,-19.32 181.4,-20.11 arc(181.09,-20.32) TAB9.6
N22696463: length 5.4
  TOP w0.114: CAB52.2 185.05,-8.85 arc(184.94,-8.92) 184.81,-8.95 184.68,-8.95 arc(184.55,-8.92) 184.44,-8.85 LAB43.2 183.89,-8.85 arc(183.78,-8.92) 183.65,-8.95 182.44,-8.95 arc(182.34,-8.93) 182.25,-8.9 arc(182.22,-8.87) 182.2,-8.85
  TOP w0.173: 182.2,-8.85 181.55,-8.2 arc(181.16,-7.94) TAB10.4
N22696550: length 9.6
  TOP w0.483: CAA9.1 JA10.1
N22696562: length 2.1
  TOP w0.483: RAA6.1 RAA7.1 CAA9.2
N22696568: length 2
  TOP w0.483: CAB53.2 RAA8.1 RAA6.2
N22696574: length 3.1
  TOP w0.483: TAB10.3 CAB53.1
N22696580: length 5.5
  TOP w0.114: CAB54.2 185.05,-9.32 arc(184.94,-9.24) 184.81,-9.22 184.68,-9.22 arc(184.55,-9.24) 184.44,-9.32 LAB43.1 183.89,-9.32 arc(183.78,-9.24) 183.65,-9.22 182.44,-9.22 arc(182.34,-9.23) 182.26,-9.27 arc(182.23,-9.29) 182.2,-9.32
  TOP w0.173: 182.2,-9.32 181.4,-10.11 arc(181.09,-10.32) TAB10.6
N22697544: length 5.4
  TOP w0.114: CAB55.2 185.05,1.15 arc(184.94,1.08) 184.81,1.05 184.68,1.05 arc(184.55,1.08) 184.44,1.15 LAB45.2 183.89,1.15 arc(183.78,1.08) 183.65,1.05 182.44,1.05 arc(182.34,1.07) 182.25,1.1 arc(182.22,1.13) 182.2,1.15
  TOP w0.173: 182.2,1.15 181.55,1.8 arc(181.16,2.05) TAB11.4
N22697619: length 9.6
  TOP w0.483: CAA14.1 JA11.1
N22697639: length 2.1
  TOP w0.483: RAA10.1 RAA11.1 CAA14.2
N22697645: length 2
  TOP w0.483: CAB56.2 RAA12.1 RAA10.2
N22697651: length 3.1
  TOP w0.483: TAB11.3 CAB56.1
N22697657: length 5.5
  TOP w0.114: CAB57.2 185.05,0.68 arc(184.94,0.76) 184.81,0.78 184.68,0.78 arc(184.55,0.76) 184.44,0.68 LAB45.1 183.89,0.68 arc(183.78,0.76) 183.65,0.78 182.44,0.78 arc(182.34,0.77) 182.26,0.73 arc(182.23,0.71) 182.2,0.68
  TOP w0.173: 182.2,0.68 181.4,-0.11 arc(181.09,-0.32) TAB11.6
N22697841: length 5.4
  TOP w0.114: CAB58.2 185.05,11.15 arc(184.94,11.08) 184.81,11.05 184.68,11.05 arc(184.55,11.08) 184.44,11.15 LAB47.2 183.89,11.15 arc(183.78,11.08) 183.65,11.05 182.44,11.05 arc(182.34,11.07) 182.25,11.1 arc(182.22,11.13) 182.2,11.15
  TOP w0.173: 182.2,11.15 181.55,11.8 arc(181.16,12.05) TAB12.4
N22697916: length 9.6
  TOP w0.483: CAA19.1 JA12.1
N22697918: length 2.1
  TOP w0.483: CAA19.2 RAA15.1 RAA14.1
N22697942: length 2
  TOP w0.483: CAB59.2 RAA16.1 RAA14.2
N22697948: length 3.1
  TOP w0.483: TAB12.3 CAB59.1
N22697954: length 5.5
  TOP w0.114: CAB60.2 185.05,10.68 arc(184.94,10.76) 184.81,10.78 184.68,10.78 arc(184.55,10.76) 184.44,10.68 LAB47.1 183.89,10.68 arc(183.78,10.76) 183.65,10.78 182.44,10.78 arc(182.34,10.77) 182.26,10.73 arc(182.23,10.71) 182.2,10.68
  TOP w0.173: 182.2,10.68 181.4,9.89 arc(181.09,9.68) TAB12.6
N22698936: length 5.4
  TOP w0.114: CAB61.2 185.05,21.15 arc(184.94,21.08) 184.81,21.05 184.68,21.05 arc(184.55,21.08) 184.44,21.15 LAB49.2 183.89,21.15 arc(183.78,21.08) 183.65,21.05 182.44,21.05 arc(182.34,21.07) 182.25,21.1 arc(182.22,21.13) 182.2,21.15
  TOP w0.173: 182.2,21.15 181.55,21.8 arc(181.16,22.05) TAB13.4
N22699019: length 9.6
  TOP w0.483: CAA24.1 JA13.1
N22699033: length 2.1
  TOP w0.483: CAA24.2 RAA19.1 RAA18.1
N22699037: length 2
  TOP w0.483: CAB62.2 RAA20.1 RAA18.2
N22699043: length 3.1
  TOP w0.483: TAB13.3 CAB62.1
N22699049: length 5.5
  TOP w0.114: CAB63.2 185.05,20.68 arc(184.94,20.76) 184.81,20.78 184.68,20.78 arc(184.55,20.76) 184.44,20.68 LAB49.1 183.89,20.68 arc(183.78,20.76) 183.65,20.78 182.44,20.78 arc(182.34,20.77) 182.26,20.73 arc(182.23,20.71) 182.2,20.68
  TOP w0.173: 182.2,20.68 181.4,19.89 arc(181.09,19.68) TAB13.6
N22699217: length 5.4
  TOP w0.114: CAB64.2 185.05,31.15 arc(184.94,31.08) 184.81,31.05 184.68,31.05 arc(184.55,31.08) 184.44,31.15 LAB51.2 183.89,31.15 arc(183.78,31.08) 183.65,31.05 182.44,31.05 arc(182.34,31.07) 182.25,31.1 arc(182.22,31.13) 182.2,31.15
  TOP w0.173: 182.2,31.15 181.55,31.8 arc(181.16,32.05) TAB14.4
N22699300: length 9.6
  TOP w0.483: JA14.1 CAA29.1
N22699302: length 2.1
  TOP w0.483: RAA22.1 RAA23.1 CAA29.2
N22699318: length 2
  TOP w0.483: RAA22.2 RAA24.1 CAB65.2
N22699324: length 3.1
  TOP w0.483: TAB14.3 CAB65.1
N22699330: length 5.5
  TOP w0.114: CAB66.2 185.05,30.68 arc(184.94,30.76) 184.81,30.78 184.68,30.78 arc(184.55,30.76) 184.44,30.68 LAB51.1 183.89,30.68 arc(183.78,30.76) 183.65,30.78 182.44,30.78 arc(182.34,30.77) 182.26,30.73 arc(182.23,30.71) 182.2,30.68
  TOP w0.173: 182.2,30.68 181.4,29.89 arc(181.09,29.68) TAB14.6
N22700324: length 5.4
  TOP w0.114: CAB70.2 185.05,51.15 arc(184.94,51.08) 184.81,51.05 184.68,51.05 arc(184.55,51.08) 184.44,51.15 LAB55.2 183.89,51.15 arc(183.78,51.08) 183.65,51.05 182.44,51.05 arc(182.34,51.07) 182.25,51.1 arc(182.22,51.13) 182.2,51.15
  TOP w0.173: 182.2,51.15 181.55,51.8 arc(181.16,52.05) TAB16.4
N22700407: length 9.6
  TOP w0.483: CAA39.1 JA16.1
N22700409: length 2.1
  TOP w0.483: RAA30.1 RAA31.1 CAA39.2
N22700425: length 2
  TOP w0.483: RAA30.2 RAA32.1 CAB71.2
N22700431: length 3.1
  TOP w0.483: CAB71.1 TAB16.3
N22700437: length 5.5
  TOP w0.114: CAB72.2 185.05,50.68 arc(184.94,50.76) 184.81,50.78 184.68,50.78 arc(184.55,50.76) 184.44,50.68 LAB55.1 183.89,50.68 arc(183.78,50.76) 183.65,50.78 182.44,50.78 arc(182.34,50.77) 182.26,50.73 arc(182.23,50.71) 182.2,50.68
  TOP w0.173: 182.2,50.68 181.4,49.89 arc(181.09,49.68) TAB16.6
N22700663: length 5.4
  TOP w0.114: CAB67.2 185.05,41.15 arc(184.94,41.08) 184.81,41.05 184.68,41.05 arc(184.55,41.08) 184.44,41.15 LAB53.2 183.89,41.15 arc(183.78,41.08) 183.65,41.05 182.44,41.05 arc(182.34,41.07) 182.25,41.1 arc(182.22,41.13) 182.2,41.15
  TOP w0.173: 182.2,41.15 181.55,41.8 arc(181.16,42.05) TAB15.4
N22700760: length 9.6
  TOP w0.483: CAA34.1 JA15.1
N22700762: length 2.1
  TOP w0.483: RAA26.1 RAA27.1 CAA34.2
N22700790: length 2
  TOP w0.483: RAA26.2 RAA28.1 CAB68.2
N22700796: length 3.1
  TOP w0.483: CAB68.1 TAB15.3
N22700802: length 5.5
  TOP w0.114: CAB69.2 185.05,40.68 arc(184.94,40.76) 184.81,40.78 184.68,40.78 arc(184.55,40.76) 184.44,40.68 LAB53.1 183.89,40.68 arc(183.78,40.76) 183.65,40.78 182.44,40.78 arc(182.34,40.77) 182.26,40.73 arc(182.23,40.71) 182.2,40.68
  TOP w0.173: 182.2,40.68 181.4,39.89 arc(181.09,39.68) TAB15.6
N22703406: length 2.2
  BOTTOM w0.173: CAB74.1 259.44,-22.91 R92.1 259.44,-25.05 R91.2
N22703440: length 2.4
  BOTTOM w0.173: R89.1 R90.1 R88.2
N22704009: length 3.2
  BOTTOM w0.173: R88.1 JA20.1
N22704037: length 3.2
  BOTTOM w0.173: R91.1 JA21.1
N22704041: length 3.8
  BOTTOM w0.173: R93.1 JA22.1
N22704055: length 3.9
  BOTTOM w0.173: R76.2 D14.3 212.02,-23.92 R77.1
N22704067: length 3.9
  BOTTOM w0.173: R82.2 D16.3 217.93,-23.92 R83.1
N22704077: length 3.3
  BOTTOM w0.173: R77.2 212.02,-30.29 JA18.1
N22704079: length 3.3
  BOTTOM w0.173: JA19.1 217.94,-26.99 R83.2
N22849015: length 2.1
  BOTTOM w0.381: RP129.2 308.56,140.65 JFA6.1
N210349064: length 3.1
  TOP w0.173: RG2.2 232.54,-19.97 233.04,-19.47 UG1.20
N210349065: length 3
  TOP w0.173: RG3.2 233.95,-20.27 234.14,-20.08 UG1.21
N210349066: length 3
  TOP w0.173: FBA1.1 235.56,-20.32 235.24,-20 UG1.22
N210349067: length 3.3
  TOP w0.173: FBA2.1 237.27,-20.68 236.34,-19.75 UG1.23
N213200537: length 4.6
  TOP w0.173: J12.8 v1(360.34,83.53)
  BOTTOM w0.173: R36.1 362.19,81.68 v1(360.34,83.53)
N213200538: length 4.2
  TOP w0.173: J12.9 360.81,84.33 v1(361.61,85.13)
  BOTTOM w0.173: v1(361.61,85.13) 361.84,84.89 R37.1
N223618380: length 7.3
  TOP w0.114: C76.1 338.65,-5.62 arc(338.54,-5.69) 338.41,-5.72 334.32,-5.72 arc(334.27,-5.71) 334.23,-5.69 333.94,-5.39 arc(333.81,-5.31) 333.67,-5.28 333.19,-5.28 arc(333.12,-5.26) 333.06,-5.23 333.05,-5.21 arc(332.99,-5.17) 332.93,-5.16 J17.53
N223618460: length 7.3
  TOP w0.114: J17.55 332.93,-5.66 arc(332.99,-5.65) 333.05,-5.61 333.06,-5.59 arc(333.12,-5.56) 333.19,-5.54 333.67,-5.54 arc(333.71,-5.55) 333.75,-5.58 334.05,-5.87 arc(334.17,-5.96) 334.32,-5.99 338.41,-5.99 arc(338.54,-6.01) 338.65,-6.09 C77.1
N223618760: length 1.4
  BOTTOM w0.508: D8.1 R62.2
N223630967: length 7.7
  TOP w0.152: C88.2 389.78,45.12 389.44,44.79 389.44,44.46 389.71,44.19 390.14,44.19 390.36,43.97 390.36,43.54 390.58,43.32 391,43.32 391.22,43.1 391.22,42.68 391.93,41.97 393.34,41.97 393.49,42.12 J18.8
N223630968: length 7.7
  TOP w0.152: C89.2 388.8,45.12 389.13,44.79 389.13,44.33 391.8,41.67 393.34,41.67 393.49,41.51 J18.9
N223631803: length 2.2
  TOP w0.173: R73.1 U17.4
N223632060: length 1.4
  TOP w0.173: R72.1 D11.1
N225299922: length 2.9
  TOP w0.173: R4.2 390.7,2.11 390.2,2.61 U2.6
N225299926: length 3.1
  TOP w0.173: U2.14 389.72,6.61 390.95,7.83 R5.1
N225300261: length 1.4
  TOP w0.173: R3.2 U3.3
N225301861: length 1.4
  TOP w0.173: R6.2 U4.3
N225303331: length 1.4
  TOP w0.173: R11.2 U5.3
N225303874: length 1.3
  TOP w0.173: J4.A5 v1(400.25,7.12)
  BOTTOM w0.173: R13.1 400.26,7.12 v1(400.25,7.12)
N225305011: length 1.4
  TOP w0.173: R12.2 U6.3
N225306131: length 1.4
  TOP w0.173: R14.2 U7.3
N225307991: length 1.4
  TOP w0.173: R16.2 U8.3
N226131680: length 2
  TOP w0.381: Q1.1 R24.2
N226131900: length 2
  TOP w0.381: Q2.1 R27.2
N226132090: length 2
  TOP w0.381: Q3.1 R30.2
N226132280: length 2
  TOP w0.381: Q4.1 R33.2
N226132550: length 6.5
  TOP w0.381: R23.2 280.8,-24.53 282.13,-25.86 J5.1
N226132710: length 1.6
  TOP w0.381: R22.2 286.45,-21.29 286.1,-21.64 D4.1
N226132880: length 1.6
  TOP w0.381: R25.2 295.29,-21.29 294.94,-21.64 D5.1
N226132960: length 1.6
  TOP w0.381: R28.2 304.08,-21.29 303.73,-21.64 D6.1
N226133040: length 1.6
  TOP w0.381: D7.1 312.64,-21.64 312.99,-21.29 R31.2
N226133650: length 6.5
  TOP w0.381: R26.2 289.66,-24.59 291,-25.92 J6.1
N226133910: length 6.5
  TOP w0.381: R29.2 298.53,-24.56 299.86,-25.9 J7.1
N226134170: length 6.5
  TOP w0.381: R32.2 307.39,-24.53 308.73,-25.86 J8.1
N227036900: length 1.3
  TOP w0.381: D12.1 R74.2
N227036901: length 2.3
  TOP w0.381: D12.2 350.49,64.47 350.88,64.85 Q5.3
N227037101: length 1.4
  TOP w0.173: Q5.1 R75.1
N227037300: length 1.3
  TOP w0.381: D13.1 R78.2
N227037301: length 2.2
  TOP w0.381: Q6.3 350.95,59.72 350.49,59.26 D13.2
N227037501: length 1.4
  TOP w0.173: Q6.1 R79.1
N227037700: length 1.3
  TOP w0.508: D15.1 R80.2
N227037701: length 2.2
  TOP w0.381: Q7.3 350.95,54.59 350.49,54.13 D15.2
N227037901: length 1.4
  TOP w0.173: Q7.1 R81.1
N227038121: length 3.6
  TOP w0.173: R84.2 397.03,-4.5 397.39,-4.13 SWC1.2
N227038123: length 4.2
  TOP w0.173: SWC1.4 398.21,-1.59 396.39,-3.4 R85.2
N227038461: length 2.3
  TOP w0.173: SWC2.2 R86.2
N227038671: length 2.5
  TOP w0.173: R87.2 355.91,72.16 SWC3.2
N227138570: length 4.2
  TOP w0.173: v1(381.04,58.29) U12.7
  BOTTOM w0.173: R48.2 v1(381.04,58.29)
N227140082: length 3.2
  TOP w0.203: 378.6,60.75 379.04,61.18 U12.2
  TOP w0.508: 378.6,60.75 378.4,60.55 378.4,60.55 377.64,59.79 FB9.2
N227630989: length 3.9
  TOP w0.173: C53.1 J16.1
N229316351: length 2.2
  TOP w0.173: R208.1 341.64,36.56 341.98,36.9 Y7.1
N231249851: length 3.4
  TOP w0.173: v1(373.27,127.68) J40.3
  BOTTOM w0.173: R185.1 372.53,128.42 v1(373.27,127.68)
N231249931: length 2.6
  TOP w0.173: J40.2 v1(374.17,126.88)
  BOTTOM w0.173: R184.1 374.91,127.62 v1(374.17,126.88)
N231250011: length 2.4
  TOP w0.173: J40.4 v1(374.17,128.48)
  BOTTOM w0.173: R186.1 374.36,128.67 v1(374.17,128.48)
N231250091: length 3.2
  TOP w0.173: J40.5 v1(373.27,129.28)
  BOTTOM w0.173: R187.1 373.08,129.47 v1(373.27,129.28)
N231250171: length 2.4
  TOP w0.173: J40.6 v1(374.17,130.08)
  BOTTOM w0.173: R188.1 374.52,129.73 v1(374.17,130.08)
N231250401: length 3.3
  TOP w0.173: J40.7 v1(373.27,130.88)
  BOTTOM w0.173: v1(373.27,130.88) 372.91,130.52 R189.1
N231250481: length 3.8
  TOP w0.173: J40.9 v1(373.27,132.48)
  BOTTOM w0.173: R190.1 372.87,131.57 373.27,131.97 v1(373.27,132.48)
N231250561: length 2.9
  TOP w0.173: J40.8 v1(374.17,131.68)
  BOTTOM w0.173: v1(374.17,131.68) 374.17,131.35 374.73,130.78 R191.1
N2132005310: length 4.1
  TOP w0.173: v1(361.61,86.73) 360.81,85.93 J12.11
  BOTTOM w0.173: v1(361.61,86.73) R34.1
N2132005311: length 4.2
  TOP w0.173: J12.12 v1(360.34,86.73)
  BOTTOM w0.173: R35.1 361.26,85.8 v1(360.34,86.73)
N2132005326: length 3.5
  TOP w0.173: v1(353.64,85.53) 354.44,86.33 J12.27
  BOTTOM w0.173: R38.1 v1(353.64,85.53)
N2132005327: length 2.1
  TOP w0.173: v1(354.71,85.55) 354.73,85.53 J12.28
  BOTTOM w0.173: R39.1 v1(354.71,85.55)
N2132005330: length 6.1
  TOP w0.173: J12.31 353.95,83.13 351.71,80.89 R40.1
N2236203114: length 7.8
  TOP w0.114: J17.29 332.82,0.84 arc(332.89,0.83) 332.94,0.79 332.96,0.77 arc(333.01,0.74) 333.08,0.72 333.43,0.72 arc(333.48,0.73) 333.51,0.76 333.81,1.05 arc(333.84,1.09) 333.84,1.14 333.84,1.3 arc(333.87,1.44) 333.96,1.57 334.21,1.82 arc(334.39,1.94) 334.6,1.98 338.41,1.98 arc(338.54,2.01) 338.65,2.08 C68.1
N2236203115: length 7.8
  TOP w0.114: J17.31 332.83,0.34 arc(332.9,0.35) 332.95,0.39 332.97,0.41 arc(333.02,0.44) 333.09,0.46 333.43,0.46 arc(333.58,0.49) 333.7,0.57 334,0.87 arc(334.08,0.99) 334.11,1.14 334.11,1.3 arc(334.12,1.34) 334.15,1.38 334.4,1.63 arc(334.49,1.69) 334.6,1.71 338.4,1.71 arc(338.54,1.69) 338.65,1.61 C69.1
N2236203117: length 4
  TOP w0.114: C70.1 335.09,0.15 arc(334.98,0.08) 334.85,0.05 334.3,0.05 arc(334.15,0.02) 334.03,-0.06 333.92,-0.17 arc(333.84,-0.29) 333.81,-0.44 333.81,-0.53 arc(333.79,-0.6) 333.75,-0.67 333.71,-0.71 arc(333.63,-0.76) 333.54,-0.78 333.08,-0.78 arc(333.01,-0.76) 332.96,-0.73 332.94,-0.71 arc(332.89,-0.67) 332.82,-0.66 J17.35
N2236203118: length 4
  TOP w0.114: C71.1 335.09,-0.31 arc(334.98,-0.24) 334.85,-0.21 334.3,-0.21 arc(334.25,-0.22) 334.22,-0.25 334.11,-0.36 arc(334.08,-0.39) 334.07,-0.44 334.07,-0.53 arc(334.04,-0.71) 333.94,-0.85 333.9,-0.9 arc(333.73,-1.01) 333.54,-1.04 333.09,-1.04 arc(333.02,-1.06) 332.97,-1.09 332.95,-1.11 arc(332.9,-1.15) 332.83,-1.16 331.94,-1.16 J17.37
N2236203120: length 7.2
  TOP w0.114: C72.1 338.65,-1.77 arc(338.54,-1.84) 338.41,-1.87 334.15,-1.87 arc(334.01,-1.9) 333.88,-1.98 333.62,-2.24 arc(333.58,-2.27) 333.54,-2.28 333.08,-2.28 arc(333.01,-2.26) 332.96,-2.23 332.94,-2.21 arc(332.89,-2.17) 332.82,-2.16 J17.41
N2236203121: length 7.2
  TOP w0.114: C73.1 338.65,-2.24 arc(338.54,-2.16) 338.41,-2.14 334.15,-2.14 arc(334.11,-2.15) 334.07,-2.17 333.81,-2.43 arc(333.69,-2.51) 333.54,-2.54 333.09,-2.54 arc(333.02,-2.56) 332.97,-2.59 332.95,-2.61 arc(332.9,-2.65) 332.83,-2.66 J17.43
N2236203123: length 3.5
  TOP w0.114: C74.1 335.09,-3.69 arc(334.98,-3.77) 334.85,-3.79 333.11,-3.79 arc(333.03,-3.78) 332.97,-3.74 332.95,-3.72 arc(332.88,-3.68) 332.81,-3.66 J17.47
N2236203124: length 3.5
  TOP w0.114: J17.49 331.94,-4.16 332.84,-4.16 arc(332.9,-4.15) 332.94,-4.12 332.96,-4.1 arc(333.01,-4.07) 333.06,-4.06 334.85,-4.06 arc(334.98,-4.09) 335.09,-4.16 C75.1
N2236302324: length 2.4
  TOP w0.173: U15.24 384.75,41.11 384.58,41.27 R68.2
N2236302326: length 4.5
  TOP w0.173: U15.22 385.46,39.56 386.05,40.16 386.05,42.36 R67.2
N2236302328: length 4.8
  TOP w0.254: U15.20 385.95,38.56 v1(386.44,39.06)
  BOTTOM w0.254: C90.1 385.55,37.19 386.44,38.08 v1(386.44,39.06)
N2252999246: length 3.3
  TOP w0.173: U2.4 390.54,1.61 391.23,0.92 FB1.2
N2252999247: length 3.2
  TOP w0.173: U2.9 389.91,4.11 390.56,4.76 FB2.2
N2253038716: length 2.9
  TOP w0.173: J4.B5 401.91,8.87 402.2,9.16 v1(402.2,9.98)
  BOTTOM w0.173: R15.1 v1(402.2,9.98)
N2276309811: length 6.7
  BOTTOM w0.508: R49.1 403.75,58.16 J16.12
N2276309813: length 6.7
  BOTTOM w0.508: R50.1 403.75,69.34 J16.13

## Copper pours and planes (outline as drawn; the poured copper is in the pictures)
+1.8V on TOP: 366.24,53.21 368.76,53.21 368.91,53.06 368.91,49.63 368.63,49.35 366.27,49.35 366.12,49.5 366.12,53.09
+1.8V on POWER07: 355.04,55.05 382.7,55.05 383.22,54.53 383.22,32.53 383.24,32.46 383.28,32.4 385.59,30.08 385.65,30.04 385.72,30.03 402.63,30.03 403.58,29.09 403.58,-13.45 335.46,-13.45 332.86,-10.84 332.86,-0.19 334.95,1.91 354.77,1.91 354.85,1.92 354.91,1.96 356.75,3.8 356.79,3.86 356.81,3.94 356.81,34.8 356.79,34.87 356.75,34.93 356.12,35.57 356.05,35.61 355.98,35.62 354.28,35.62 353.76,36.15 353.76,53.77
+3.3V on TOP: 345.01,28.07 344.92,28.16 344.92,30.27 345.05,30.41 347.75,30.41 347.93,30.59 347.93,31.9 347.65,32.18 346.89,32.18 346.81,32.26 346.81,33.05 346.86,33.1 350.98,33.1 351.15,32.92 351.15,28.47 350.75,28.07
+3.3V on TOP: 350.53,22.45 350.36,22.28 341.58,22.28 341.53,22.33 341.53,23.47 341.66,23.6 346.41,23.6 346.71,23.9 350.43,23.9 350.53,23.8
+3.3V on TOP: 325.28,6.95 325.18,6.85 323.46,6.85 323.37,6.76 323.37,6.34 323.35,6.32 323.35,5.14 325.2,5.14 325.25,5.09 325.25,3.61 325.17,3.53 323.46,3.53 323.06,3.13 323.06,-8.91 323.51,-9.36 325.17,-9.36 325.38,-9.56 325.38,-11.1 324.87,-11.61 320.12,-11.61 319.66,-11.15 319.66,7.67 320.49,8.5 325.14,8.5 325.28,8.36
+3.3V on TOP: 353.67,128.7 355.19,128.7 355.45,128.45 355.45,126.8 355.19,126.54 353.67,126.54 353.42,126.8 353.42,128.45
+3.3V on TOP: 327.07,108.77 331.11,108.77 331.37,108.51 331.37,104.34 331.17,104.15 327.18,104.15 326.91,104.41 326.91,108.61
+3.3V on TOP: 353.16,132.51 355.07,132.51 355.45,132.13 355.45,129.46 355.19,129.21 353.03,129.21 352.78,129.46 352.78,132.13
+3.3V on BOTTOM: 346.18,88.19 343.26,88.19 343,87.93 343,82.86 343.34,82.52 345.97,82.52 346.18,82.73
+3.3V on BOTTOM: 321.23,5.89 321.84,5.89 322,5.74 322,3.1 322.22,2.87 323.62,2.87 323.85,3.1 323.85,7.82 323.65,8.03 321.34,8.03 321.08,7.77 321.08,6.05
+3.3V on BOTTOM: 346.79,28.19 346.61,28.37 346.61,30 346.81,30.2 347.68,30.2 347.9,30.42 347.9,31.68 348.08,31.86 349.78,31.86 349.97,31.67 349.97,28.7 349.47,28.19
+3.3V on BOTTOM: 353.35,84.38 354.86,84.38 355.12,84.13 355.12,83.16 354.54,82.59 352.68,82.59 352.51,82.76 352.51,83.54
+3.3V on BOTTOM: 363.04,87.07 368.05,87.07 368.3,86.82 368.3,82.63 368.17,82.5 367.41,82.5 367.28,82.63 367.28,84.4 367.16,84.53 363.09,84.53 362.97,84.66 362.97,87
+3.3V on ART03: 378.87,46.06 366.79,33.99 347.12,33.99 345.77,32.64 345.77,-2.26 327.76,-20.27 278.38,-20.27 277.34,-21.31 256.54,-21.31 254.9,-22.95 170.55,-22.95 170.03,-23.47 170.03,-30.66 170.94,-31.57 395.12,-31.57 396.2,-30.49 396.2,-8.64 395.02,-7.47 374.78,-7.47 374.01,-6.7 374.01,17.26 374.63,17.87 397.37,17.87 397.81,18.31 397.81,35.45 397.34,35.92 389.66,35.92 389.25,36.34 389.25,45.2 388.39,46.06
+3.3V on ART05: 370.73,133.15 379.73,133.15 380.29,132.59 380.29,105.84 377.57,103.12 312.48,103.12 312.15,103.46 312.15,132.48 312.81,133.15 359.04,133.15 359.48,132.72 359.48,125.15 360.16,124.47 370,124.47 370.71,125.18 370.71,133.17
+3.3V on POWER07: 333.73,86.92 379.96,86.92 387.65,79.23 387.65,63.14 383.22,58.72 383.22,55.96 382.7,55.44 354.97,55.44 354.89,55.42 354.83,55.38 353.43,53.98 353.39,53.92 353.38,53.85 353.38,36.07 353.39,36 353.43,35.93 354.07,35.3 354.13,35.26 354.2,35.24 355.9,35.24 356.43,34.72 356.43,4.02 354.7,2.29 334.87,2.29 334.8,2.27 334.74,2.23 332.53,0.03 332.49,-0.03 332.48,-0.11 332.48,-10.92 332.49,-10.99 332.53,-11.05 335.25,-13.77 335.31,-13.81 335.38,-13.83 390.15,-13.83 391.73,-15.4 391.73,-25.07 391.34,-25.46 233.82,-25.46 233.77,-25.5 219.82,-25.5 218.86,-24.54 218.86,-15.7 269.95,35.39 330.09,35.39 330.17,35.4 330.23,35.45 330.84,36.06 330.88,36.12 330.9,36.19 330.9,84.09
+3.3V on POWER08: 328.15,107.14 356.26,107.14 357.04,106.36 357.04,22.3 355.9,21.16 328.72,21.16 327.67,22.21 327.67,106.65 ; 1 cut-out
AVDD33 on BOTTOM: 383.16,64.47 383,64.31 383,63.53 383.16,63.37 383.99,63.37 384.3,63.07 385.09,63.07 385.24,63.22 385.24,64.11 384.88,64.47
AVDDL on BOTTOM: 376.13,57.46 375.02,57.46 374.85,57.63 374.22,57.63 373.8,57.2 373.8,56.37 373.9,56.27 376.03,56.27 376.35,56.59 376.35,57.23
AVDDL on ART05: 376.45,68.53 383.75,68.53 384.1,68.18 384.1,61.66 384.13,61.63 384.06,61.63 384.06,60.14 384.04,60.09 384,60.05 384.04,60.01 384.06,59.97 384.06,58.42 384.04,58.38 384,58.34 384.04,58.3 384.06,58.26 384.06,56.84 383.07,55.85 373.93,55.85 373.34,56.45 373.34,58.96 376.83,62.45 376.83,64.72 376.04,65.51 376.04,68.12
DGND on TOP: 154.28,145.34 208.31,145.34 407.26,145.34 407.26,-33.98 154.28,-33.98 ; 20 cut-outs
DGND on BOTTOM: 357.86,92.25 358.5,91.62 358.5,86.66 357.99,86.16 353.16,86.16 352.15,85.14 352.15,81.84 351.51,81.2 348.46,81.2 348.21,81.46 348.21,90.86 349.61,92.25
DGND on BOTTOM: 387.35,35.56 390.58,35.56 390.66,35.65 390.66,36.8 389.19,38.28 389.19,39.29 388.94,39.55 387.25,39.55 387.12,39.42 387.12,35.79
DGND on BOTTOM: 154.28,145.34 407.26,145.34 407.26,-33.98 154.28,-33.98 ; 19 cut-outs
DGND on BOTTOM: 379.37,66.17 382.22,66.17 382.67,65.71 382.67,62.79 382.11,62.23 380.94,62.23 380.72,62.01 378.91,62.01 378.33,62.59 378.33,65.13
DGND on BOTTOM: 381.13,36.09 384.1,36.09 384.76,36.75 384.76,40.31 383.79,41.27 380.67,41.27 380.37,40.97 380.37,36.86
DGND on GND02, GND04, GND06, GND09, GND11: 154.28,145.34 407.26,145.34 407.26,-33.98 154.28,-33.98
DGND on ART03: 154.28,145.34 407.26,145.34 407.26,-33.98 154.28,-33.98 ; 15 cut-outs
